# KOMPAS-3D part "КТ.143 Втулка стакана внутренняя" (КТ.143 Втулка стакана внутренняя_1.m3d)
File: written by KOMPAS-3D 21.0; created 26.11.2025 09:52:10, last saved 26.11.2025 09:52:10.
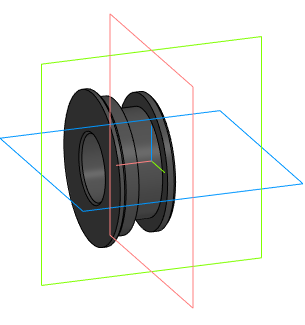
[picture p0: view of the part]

Document properties: Автор: User; Организация: User; Полное имя файла: C:\Users\User\Desktop\Pelorus PRO доработки\ЗАФИКСИРОВАЛИ\Втулка стакана внутренняя\КТ.143 Втулка стакана внутренняя_1.m3d

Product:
- Part/product: КТ.143 Втулка стакана внутренняя
    Комментарий: User

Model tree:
1. Операция без истории:1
